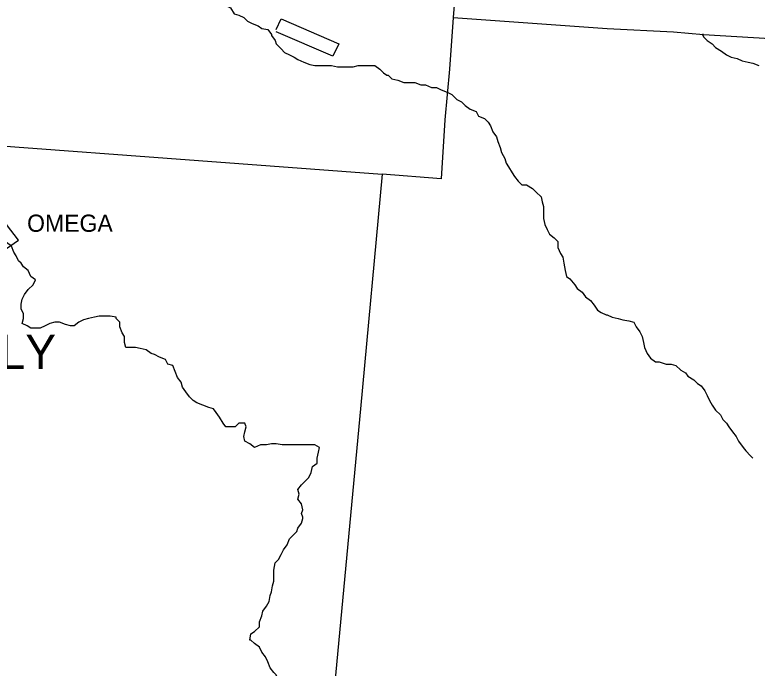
# Model space of a CAD drawing. Extents: x 0 to 40.2, y 0 to 22.
# Drawn here: x 6.366 to 7.207, y 17.808 to 18.548 of the extents above; entities that cross this region are included whole.
import ezdxf

# ---------------------------------------------------------------- set-up
doc = ezdxf.new("R2010")
doc.units = 0
doc.layers.add('Default', color=7, linetype='Continuous')

msp = doc.modelspace()

# ---------------------------------------------------------------- linework, layer by layer
at = {"layer": 'Default'}
for points in [[(6.92646, 19.46942), (6.91556, 19.30036), (6.88965, 18.91315), (6.87874, 18.74135), (6.86238, 18.54502)], [(6.5747, 18.58865), (6.57879, 18.5832), (6.58424, 18.58047), (6.58834, 18.57365), (6.59106, 18.56956), (6.59652, 18.56956), (6.60061, 18.56275), (6.6047, 18.55866), (6.61015, 18.55593), (6.61424, 18.54911), (6.61969, 18.54775), (6.62515, 18.54502), (6.62924, 18.54093), (6.63469, 18.53821), (6.64151, 18.53548), (6.6456, 18.53275), (6.65242, 18.53139), (6.65651, 18.52593), (6.65651, 18.52457)], [(6.66196, 18.53139), (6.66741, 18.54366), (6.73286, 18.51503), (6.72604, 18.50139), (6.66196, 18.52866)], [(6.86238, 18.54502), (6.86238, 18.54502), (6.85829, 18.4864), (6.85284, 18.42913), (6.84875, 18.36232), (6.78194, 18.36778)], [(6.86238, 18.54502), (7.0369, 18.53275), (7.11189, 18.52866), (7.14597, 18.52593), (7.25914, 18.51912), (7.25368, 18.46185), (7.29186, 18.45776), (7.33276, 18.45095), (7.38866, 18.44277), (7.42002, 18.4414), (7.47729, 18.4414), (7.53046, 18.4414), (7.57954, 18.43322), (7.65862, 18.42231), (7.64635, 18.25598)], [(6.65651, 18.52457), (6.6606, 18.51912), (6.66196, 18.51503), (6.66741, 18.50957), (6.6715, 18.50548), (6.67696, 18.50276), (6.68241, 18.50003), (6.6865, 18.4973), (6.69332, 18.49458), (6.70014, 18.49185), (6.70559, 18.49049), (6.71104, 18.49049), (6.71786, 18.49049), (6.72468, 18.49049), (6.73149, 18.48912), (6.73558, 18.48912), (6.7424, 18.48912), (6.74922, 18.48912), (6.75467, 18.49049), (6.76013, 18.49049), (6.76831, 18.49049), (6.77376, 18.49049), (6.77921, 18.4864), (6.7833, 18.4823), (6.78739, 18.47958), (6.78876, 18.47958)], [(7.14597, 18.52593), (7.14461, 18.52593), (7.14597, 18.52321), (7.15006, 18.51912), (7.15552, 18.51503), (7.15961, 18.51094), (7.16643, 18.50685), (7.17188, 18.50276), (7.17733, 18.50003), (7.18415, 18.49867), (7.1896, 18.49594), (7.19642, 18.49458), (7.20187, 18.49321), (7.20869, 18.49049)], [(4.7818, 18.51094), (4.91951, 18.50276), (5.49078, 18.46185), (6.12205, 18.41686), (6.78194, 18.36778)], [(6.78876, 18.47958), (6.79285, 18.47549), (6.79967, 18.47412), (6.80648, 18.4714), (6.81194, 18.4714), (6.81875, 18.4714), (6.82557, 18.46867), (6.83102, 18.46867), (6.83784, 18.46594), (6.84329, 18.46594), (6.84875, 18.46322), (6.85557, 18.46049), (6.85557, 18.46049)], [(6.85557, 18.46049), (6.86102, 18.45776), (6.86647, 18.45231), (6.87193, 18.44958), (6.87602, 18.44549), (6.88147, 18.4414), (6.88829, 18.43868), (6.89101, 18.43322), (6.89783, 18.43049), (6.90192, 18.4264), (6.90465, 18.42231), (6.90738, 18.4155), (6.91147, 18.41004), (6.91283, 18.40459), (6.91556, 18.39777), (6.91692, 18.39232), (6.92101, 18.3855), (6.92237, 18.38005), (6.9251, 18.37596), (6.92919, 18.36914), (6.93192, 18.36505), (6.93601, 18.3596), (6.9401, 18.35551), (6.94555, 18.35551), (6.94555, 18.35551)], [(6.78194, 18.36778), (6.7574, 18.10191), (6.72604, 17.76787), (6.73558, 17.76378), (6.72604, 17.65198), (6.70423, 17.39975), (6.70286, 17.36839)], [(6.94555, 18.35551), (6.95237, 18.35142), (6.95646, 18.34733), (6.96191, 18.34187), (6.96328, 18.33642), (6.96464, 18.33097), (6.96464, 18.32415), (6.96464, 18.31733), (6.966, 18.31051), (6.96873, 18.30506), (6.97146, 18.29961), (6.97691, 18.29552), (6.981, 18.29143), (6.981, 18.28461), (6.98373, 18.27779), (6.98645, 18.2737), (6.98782, 18.26688), (6.98918, 18.2587), (6.99054, 18.25189), (6.99463, 18.24916), (7.00009, 18.24234), (7.00282, 18.23825), (7.00827, 18.23416), (7.01236, 18.22871), (7.01781, 18.22462), (7.0219, 18.21916), (7.02599, 18.21371), (7.03008, 18.21098), (7.03554, 18.20826), (7.03554, 18.20826), (7.0369, 18.20826)], [(6.35519, 18.31051), (6.32656, 18.29143), (6.34019, 18.27234), (6.37019, 18.29279), (6.35655, 18.31051)], [(6.37019, 18.26961), (6.36746, 18.27506), (6.36473, 18.27916), (6.36201, 18.28597), (6.35655, 18.29006), (6.35655, 18.29415), (6.34974, 18.29552), (6.34565, 18.29143), (6.34292, 18.29415), (6.34019, 18.29961), (6.33747, 18.30233), (6.33747, 18.3037)], [(6.37564, 18.20962), (6.37291, 18.21507), (6.37291, 18.22053), (6.37428, 18.22598), (6.377, 18.23144), (6.3811, 18.23689), (6.38655, 18.24234), (6.38928, 18.2478), (6.38382, 18.25189), (6.3811, 18.2587), (6.37564, 18.26279), (6.37291, 18.26688), (6.37019, 18.26961)], [(6.48062, 18.20553), (6.47381, 18.20689), (6.46699, 18.20689), (6.46154, 18.20689), (6.45608, 18.20553), (6.44927, 18.20417), (6.44381, 18.2028), (6.43836, 18.20008), (6.43291, 18.19599), (6.42881, 18.19599), (6.42336, 18.19735), (6.41654, 18.20008), (6.41109, 18.20008), (6.40564, 18.19871), (6.40018, 18.19599), (6.39473, 18.19326), (6.38928, 18.19326), (6.38382, 18.19326), (6.37973, 18.19599), (6.37428, 18.19871), (6.37564, 18.20417), (6.37564, 18.20826), (6.37564, 18.20962)], [(6.49153, 18.17144), (6.49017, 18.1769), (6.49017, 18.18372), (6.48744, 18.18781), (6.48472, 18.19462), (6.48472, 18.20008), (6.48062, 18.20417), (6.48062, 18.20417), (6.48062, 18.20553)], [(7.0369, 18.20826), (7.04235, 18.20553), (7.04917, 18.20417), (7.05463, 18.2028), (7.06144, 18.20144), (7.0669, 18.20008), (7.06962, 18.19462), (7.07371, 18.18917), (7.07644, 18.18372), (7.0778, 18.1769), (7.07917, 18.17144), (7.08189, 18.16463), (7.08598, 18.15917), (7.09144, 18.15508), (7.09553, 18.15508), (7.10371, 18.15236), (7.10916, 18.15236), (7.11462, 18.15099), (7.12007, 18.14554), (7.12552, 18.14281), (7.12825, 18.13872), (7.13507, 18.13463), (7.13916, 18.13054), (7.14325, 18.12782)], [(6.54743, 18.14418), (6.54471, 18.15099), (6.53925, 18.15236), (6.53653, 18.15781), (6.52971, 18.16054), (6.52425, 18.16326), (6.52016, 18.16463), (6.51471, 18.16872), (6.50789, 18.17008), (6.50244, 18.17144), (6.49562, 18.17144), (6.4929, 18.17144), (6.49153, 18.17144)], [(6.69196, 17.9792), (6.69059, 17.98329), (6.69196, 17.98738), (6.69059, 17.9942), (6.6865, 17.99965), (6.68786, 18.00511), (6.6865, 18.01056), (6.69059, 18.01601), (6.69468, 18.02011), (6.69877, 18.0242), (6.7015, 18.02965), (6.70286, 18.03647), (6.70832, 18.04056), (6.70832, 18.04601), (6.70968, 18.05283), (6.71104, 18.05828), (6.70559, 18.06101), (6.70014, 18.06101), (6.69196, 18.06101), (6.6865, 18.06101), (6.67968, 18.06101), (6.67423, 18.06101), (6.66878, 18.06101), (6.66196, 18.06237), (6.65651, 18.06237), (6.65105, 18.06101), (6.64424, 18.06101), (6.63742, 18.05828), (6.63196, 18.06237), (6.62651, 18.0651), (6.62515, 18.07055), (6.62651, 18.07601), (6.62787, 18.08146), (6.62651, 18.08555), (6.61969, 18.08555), (6.6156, 18.08146), (6.61015, 18.08146), (6.6047, 18.08146), (6.60197, 18.08555), (6.59788, 18.09237), (6.59379, 18.09782), (6.59106, 18.10191), (6.58561, 18.10327), (6.57879, 18.106), (6.57197, 18.10873), (6.56788, 18.11145), (6.56379, 18.11554), (6.5597, 18.121), (6.55561, 18.12645), (6.55425, 18.13191), (6.55016, 18.13736), (6.54743, 18.14418), (6.54743, 18.14418), (6.54743, 18.14418), (6.54743, 18.14418)], [(7.14325, 18.12782), (7.14734, 18.12236), (7.15006, 18.11691), (7.15279, 18.11145), (7.15552, 18.106), (7.15961, 18.10055), (7.16506, 18.09509), (7.16779, 18.08964), (7.17188, 18.08555), (7.17461, 18.08146), (7.1787, 18.07601), (7.18279, 18.07055), (7.18551, 18.0651), (7.19097, 18.05828), (7.19369, 18.05419), (7.19915, 18.04874), (7.20187, 18.04601), (7.20187, 18.04601)], [(6.63196, 17.84013), (6.63333, 17.84695), (6.63742, 17.84968), (6.64287, 17.85513), (6.64287, 17.86058), (6.6456, 17.8674), (6.64696, 17.87286), (6.65105, 17.87831), (6.65378, 17.88376), (6.65514, 17.89058), (6.65651, 17.89467), (6.65787, 17.90149), (6.65923, 17.90694), (6.65923, 17.91376), (6.65923, 17.91921), (6.6606, 17.92739), (6.66469, 17.93148), (6.66741, 17.93694), (6.67014, 17.94239), (6.67423, 17.94784), (6.67696, 17.95466), (6.68105, 17.95875), (6.68514, 17.96284), (6.6865, 17.96693), (6.69059, 17.97239), (6.69196, 17.97784), (6.69196, 17.9792)], [(6.66469, 17.78696), (6.66469, 17.79514), (6.66196, 17.80059), (6.65923, 17.80332), (6.65514, 17.80877), (6.65242, 17.81559), (6.64969, 17.82105), (6.6456, 17.8265), (6.64287, 17.83195), (6.63742, 17.83604), (6.63333, 17.84013), (6.63196, 17.84013)]]:
    msp.add_lwpolyline(points, dxfattribs=at)

# ---------------------------------------------------------------- texts
for s, height, p in [('OMEGA', 0.019502, (6.37973, 18.30233)), ('WAVERLY', 0.039005, (6.15749, 18.1469))]:
    msp.add_text(s, height=height, dxfattribs=at).set_placement(p)

doc.saveas('drawing.dxf')
